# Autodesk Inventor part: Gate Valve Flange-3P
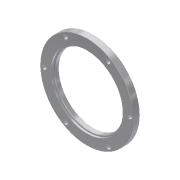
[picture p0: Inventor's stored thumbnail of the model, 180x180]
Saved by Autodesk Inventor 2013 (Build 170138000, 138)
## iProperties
Created: 2012-05
Part Number: Gate Valve Flange-3P
Material: Stainless Steel, 316
Description: GATE VALVE FLANGE
Document SubType Name: Modeling
Designer: Henneborn
Manufacturer: Standard
Standards Organization: Custom
Density: 7.9 g/cm^3
Rohmasse: 7,2" O.D.  x 0,5" made of sheet
Author: vm
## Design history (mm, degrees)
sketch "Sketch1"
  geometry: C1 r 91.44 at (0, 0); C2 r 67.31 at (0, 0); 1 further point
  constraints: 2 centre point, 1 coincident
  dimensions: "d0" = 182.88 diameter of C1; "d25" = 134.62 diameter of C2
extrude "Extrusion1" new body sketch "Sketch1" stored distance "d2" = 12.7; taper "d3" = 0 deg
sketch "Sketch2"
  geometry: C1 r 67.31 at (0, 0) reference; C2 r 70.65 at (0, 0)
  constraints: 1 centre point
  dimensions: "d4" = 141.3002 diameter of C2
extrude "Extrusion2" cut sketch "Sketch2" distance "d5" = 3.81; taper "d6" = 0 deg
chamfer "Chamfer1" distance "d7" = 1.016; stored, may be unused: second distance "d8" = 3.175, angle "d9" = 45 deg
chamfer "Chamfer2" distance "d10" = 0.508; stored, may be unused: second distance "d11" = 3.175, angle "d12" = 45 deg
sketch "Sketch3"
  geometry: L1 (0, 0)-(-41.91, 72.59); L2 (0, -128.016)-(0, 128.016) reference; C1 r 90.932 at (0, 0) reference; 1 further point
  constraints: 2 end point, 1 coincident
  dimensions: "d13" = 30 deg angle of L2 L1; "d14" = 83.82 distance of L1.start L1.end
hole "Hole1" sketch "Sketch3" at (-41.91, 72.59) diameter "d15" = 8.7376; stored, may be unused: countersink angle "d19" = 82 deg, drill point angle "d21" = 118 deg; dims "d16" = 12.7, "d17" = 9.525, "d18" = 6.35, "d20" = 19.05
pattern_circular "Circular Pattern1" dims angle "d24" = 360 deg
body "Solid1"
